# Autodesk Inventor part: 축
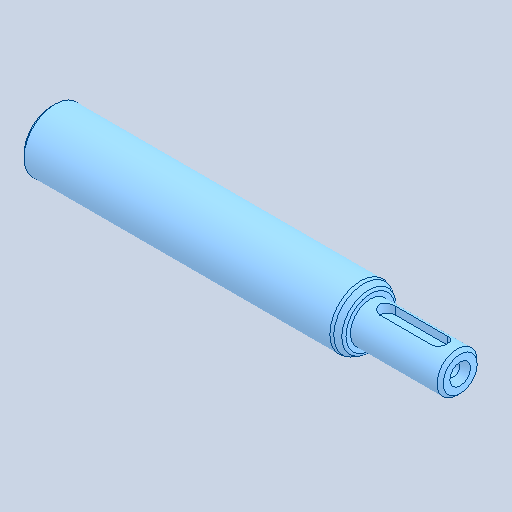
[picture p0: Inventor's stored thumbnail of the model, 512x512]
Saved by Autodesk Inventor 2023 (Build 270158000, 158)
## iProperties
Created: 2024-09
Part Number: 축
Material: 강철, 탄소
Document SubType Name: Modeling
Designer: home
Density: 7.85 g/cm^3
Appearance: 기본값
Author: jhkim
Sending System: Autodesk Inventor 2025
Preprocessor: ST-DEVELOPER v20
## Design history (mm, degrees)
feature "솔리드1"
node "솔리드2"
